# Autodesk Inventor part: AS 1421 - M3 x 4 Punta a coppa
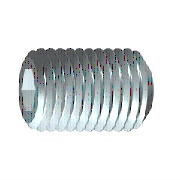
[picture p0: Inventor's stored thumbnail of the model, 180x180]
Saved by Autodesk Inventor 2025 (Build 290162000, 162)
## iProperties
Created: 2024-01
Part Number: AS 1421 - M3 x 4 Punta a coppa
Material: Acciaio, Dolce
Description: Viti di arresto ad esagono incassato metriche ISO
Document SubType Name: Modeling
Standard: AS 1421
Designer: R5800u
Standards Organization: AS
Language: it-IT
Size Designation: M3 x 4 Punta a coppa
Categories: <MemberInstance><Categories><Category DisplayName="Elementi di fissaggio" InternalName="e4da775c-781d-43d5-af7c-5136215cf5a6" Mnemonic="FSTN"><Category DisplayN
Density: 7.85 g/cm^3
Appearance: Semilucidato
IsCustomPart: 0
Author: R5800u
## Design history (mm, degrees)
revolve "Corpo" stored, may be unused: angle "d6" = 90 deg
sketch "Schizzo2"
  geometry: L1 (0.866, 0)-(0.433, -0.75); L2 (0.433, -0.75)-(-0.433, -0.75); L3 (-0.433, -0.75)-(-0.866, 0); L4 (-0.866, 0)-(-0.433, 0.75); L5 (-0.433, 0.75)-(0.433, 0.75); L6 (0.433, 0.75)-(0.866, 0); C1 r 1.5 at (0, 0) reference; A1 r 0.866 centre (0, 0) between (0.866, 0) and (0.433, -0.75) reference; 1 further point
  constraints: 12 end point, 2 point on circle, 1 coincident, 1 horizontal, 11 other
extrude "Intaglio" join sketch "Schizzo2" distance "d8" = 2 (= INTI); taper "d9" = 0 deg
workaxis "Work Axis1"
workplane "Work Plane1"
body "Solid1"
chamfer "Smusso1" distance "d10" = 0.95 (= -0.5 x SPD + 0.5 x NND); stored, may be unused: angle "d11" = 45 deg (= FAWI), second distance "d33" = 0.95 (= -0.5 x SPD + 0.5 x NND)
feature "Filettatura" dims "d14" = 4 (= NLG), "d15" = 0
chamfer "Smusso2" distance "d12" = 0.30673 (= -0.5 x GD1 + 0.5 x NND); stored, may be unused: angle "d13" = 45 deg (= FAWI), second distance "d34" = 0.30673 (= -0.5 x GD1 + 0.5 x NND)
sketch "Schizzo1"
  geometry: L1 (0.256, 0)-(1.5, 0); L2 (4, 0.866)-(4, 1.5); L3 (4, 1.5)-(0, 1.5); L4 (4, 0.866)-(2, 0.866); L5 (2, 0.866)-(1.5, 0); L6 (0, 0.55)-(0.256, 0); L7 (0, -0.3)-(0, 1.8) reference; L8 (0, 0.55)-(0, 1.5); 1 further point
  constraints: 14 end point, 2 parallel, 2 perpendicular, 2 point on line, 1 horizontal
  dimensions: "d0" = 2 distance of L2.start L4.end (= INTI); "d1" = 60 deg angle of L5 L1; "d2" = 3 diameter of L3 L1 (= NND); "d3" = 1.73205 diameter of L4 L1 (= 1.1547 x SW); "d4" = 4 distance from line of L2 L6.start (= NLG); "d5" = 65 deg angle of L1 L6 (= 0.5 x ANG); "d7" = 1.1 diameter of L6.start L1 (= SPD)
other parameters: "NND" = 3 [user parameter; used in 5 equation terms], "NLG" = 4 [user parameter; used in 2 equation terms], "INTI" = 2 [user parameter; used in 2 equation terms], "FAWI" = 45 deg [user parameter; used in 2 equation terms], "SW" = 1.5 [user parameter; used in 2 equation terms], "GD1" = 2.38655 (= THREADDIA - 1.2269 x PTC) [user parameter; used in 2 equation terms], "ANG" = 130 deg [user parameter; used in 1 equation term], "FAWI1" = 60 deg [user parameter], "SPD" = 1.1 [user parameter; used in 3 equation terms], "d16" = 0, "d35" = 0, "d37" = 0, "GUL" = 0.30673 (= 0.61345 x PTC) [user parameter], "TOA" = 30 deg [user parameter], "THREADDIA" = 3 [user parameter; used in 1 equation term], "PTC" = 0.5 [user parameter; used in 4 equation terms], "GAL" = 0.30673 (= 0.61345 x PTC) [user parameter], "E0" = 1.7325 (= 1.155 x SW) [user parameter]
